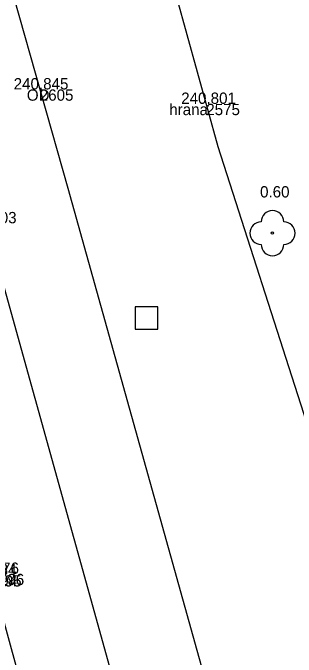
# Model space of a CAD drawing. Extents: x -599098 to -598820, y -1159597 to -1158744.
# Drawn here: x -598961.88 to -598949.37, y -1159086.94 to -1159058.42 of the extents above; entities that cross this region are included whole.
import ezdxf

# ---------------------------------------------------------------- set-up
doc = ezdxf.new("R2010")
doc.units = 0
for name, color, linetype in [('body', 7, 'Continuous'), ('druh pozemku stromy', 7, 'Continuous'), ('kresba', 7, 'Continuous'), ('kódy bodů', 7, 'Continuous'), ('výšky bodů', 7, 'Continuous'), ('značky IS', 7, 'Continuous'), ('čísla bodů', 7, 'Continuous')]:
    doc.layers.add(name, color=color, linetype=linetype)

msp = doc.modelspace()

# ---------------------------------------------------------------- linework, layer by layer
at = {"layer": 'body'}
for p, q in [((-598960.689, -1159061.81), (-598960.689, -1159061.81)), ((-598953.333, -1159062.449), (-598953.333, -1159062.449))]:
    msp.add_line(p, q, dxfattribs=at)
at = {"layer": 'druh pozemku stromy'}
msp.add_circle((-598950.41, -1159068.17), 0.05, dxfattribs=at)
for centre, start, end in [((-598950.41, -1159067.67), 0, 180), ((-598950.91, -1159068.17), 90, 270), ((-598949.91, -1159068.17), 270, 90), ((-598950.41, -1159068.67), 180, 0)]:
    msp.add_arc(centre, 0.5, start, end, dxfattribs=at)
at = {"layer": 'kresba'}
for p, q in [((-598964.644, -1159047.801), (-598959.455, -1159066.177)), ((-598952.81, -1159064.352), (-598956.548, -1159050.744)), ((-598959.455, -1159066.177), (-598944.8, -1159118.74)), ((-598963.201, -1159067.235), (-598948.308, -1159120.805)), ((-598962.864, -1159083.254), (-598959.826, -1159094.331))]:
    msp.add_line(p, q, dxfattribs=at)
msp.add_lwpolyline([(-598938.67, -1159109.76), (-598949.024, -1159076.155), (-598952.81, -1159064.352)], dxfattribs=at)
at = {"layer": 'značky IS'}
msp.add_lwpolyline([(-598956.48, -1159072.43), (-598955.48, -1159072.43), (-598955.48, -1159071.43), (-598956.48, -1159071.43)], close=True, dxfattribs=at)

# ---------------------------------------------------------------- texts
at = {"layer": 'druh pozemku stromy'}
msp.add_text('0.60', height=0.5, dxfattribs=at).set_placement((-598950.957, -1159066.592))
at = {"layer": 'kódy bodů'}
for s, p in [('OD', (-598961.261, -1159062.31)), ('hrana', (-598954.969, -1159062.949))]:
    msp.add_text(s, height=0.5, dxfattribs=at).set_placement(p)
at = {"layer": 'výšky bodů'}
for s, p in [('240.845', (-598961.841, -1159061.81)), ('240.801', (-598954.441, -1159062.449)), ('240.584', (-598964.134, -1159083.315)), ('240.676', (-598964.024, -1159083.254))]:
    msp.add_text(s, height=0.5, dxfattribs=at).set_placement(p)
at = {"layer": 'čísla bodů'}
for s, p in [('2605', (-598960.689, -1159062.31)), ('2575', (-598953.333, -1159062.949)), ('2603', (-598963.201, -1159067.735)), ('1194', (-598963.176, -1159083.808)), ('1195', (-598962.982, -1159083.815)), ('1196', (-598962.864, -1159083.754))]:
    msp.add_text(s, height=0.5, dxfattribs=at).set_placement(p)

doc.saveas('drawing.dxf')
